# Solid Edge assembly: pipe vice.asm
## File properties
Author: CADCIM
Template: Iso Assembly.asm
Last saved by: CADCIM
Revision: 3
Application: Solid Edge
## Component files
base.par
Screw.par
moveable jaw.par
handle.par
handle screw.par
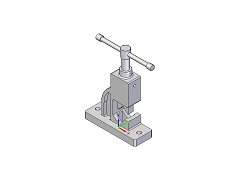
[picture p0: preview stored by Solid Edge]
